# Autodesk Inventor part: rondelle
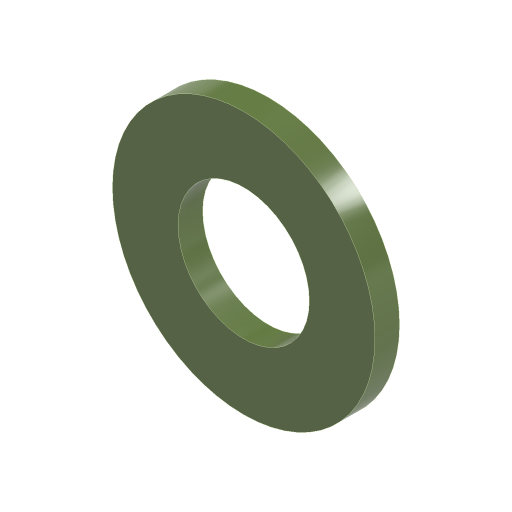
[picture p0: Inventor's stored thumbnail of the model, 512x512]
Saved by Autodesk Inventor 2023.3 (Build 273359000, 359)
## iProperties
Created: 2024-11
Part Number: rondelle
Material: Générique
Description: STEP AP203
Document SubType Name: Modeling
Designer: Thier
Density: 1 g/cm^3
Appearance: Olive foncé
Sending System: SolidWorks 2017
Preprocessor: SwSTEP 2.0
Title: rondelle.STEP
Revision Number: ANY
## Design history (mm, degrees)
feature "Base-Extrusion"
node "Solide1"
